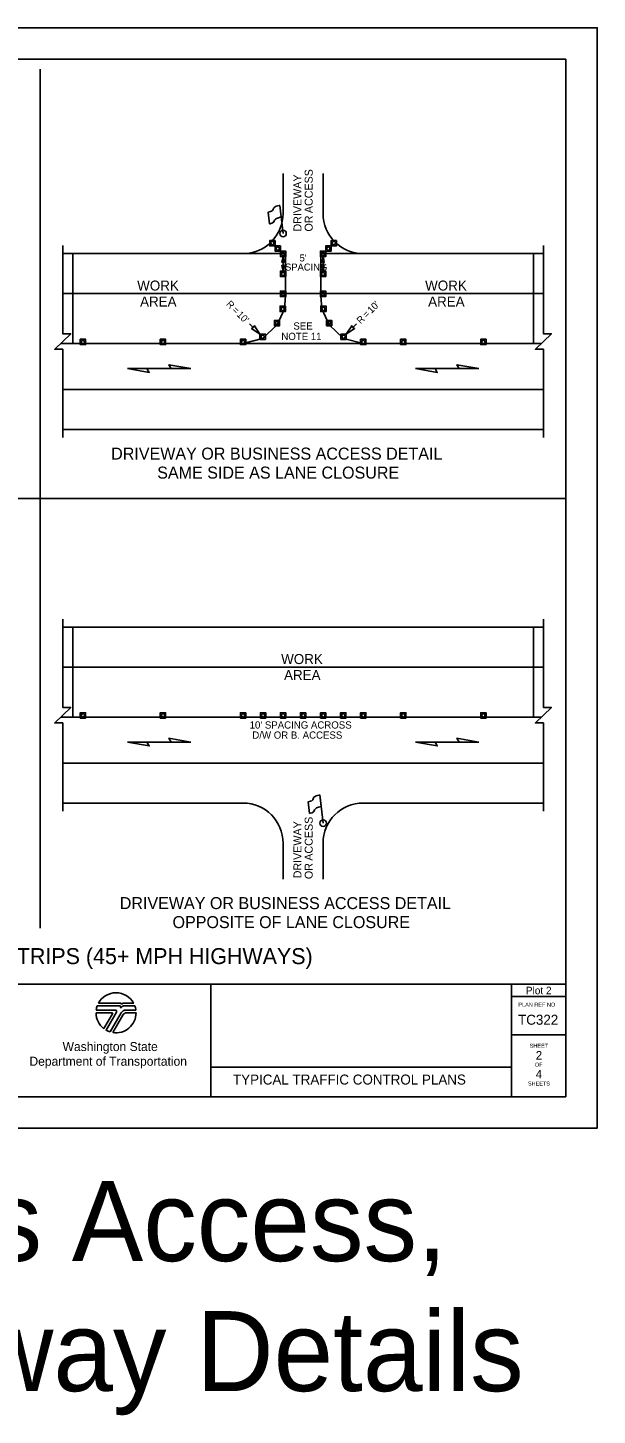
# Model space of a CAD drawing. Extents: x 99999.1 to 100095.7, y 99995 to 100010.7.
# Drawn here: x 100030.38 to 100036.06, y 99996.82 to 100010.69 of the extents above; entities that cross this region are included whole.
import ezdxf

# ---------------------------------------------------------------- set-up
doc = ezdxf.new("R2010")
doc.units = 0
for name, color, linetype in [('RD_ED_DrivewayEdge', 7, 'Continuous'), ('RD_ED_ShoulderPavedEdge', 7, 'Continuous'), ('RD_MK_LineEdgeWhite', 7, 'Continuous'), ('RD_MK_LineSkipCenter', 7, 'Continuous'), ('SH_DE_DetailHeading1Text', 7, 'Continuous'), ('SH_DE_DetailHeading2Text', 7, 'Continuous'), ('SH_GI_PlotLimits', 7, 'Continuous'), ('SH_GI_SheetBorder', 7, 'Continuous'), ('SH_GI_SheetLocationText', 7, 'Continuous'), ('SH_GI_SheetTextInCells', 7, 'Continuous'), ('SH_GI_TitleBlockText', 7, 'Continuous'), ('SH_GI_WSDOTLogo', 7, 'Continuous'), ('TR_WZ_FlaggingStation', 7, 'Continuous'), ('TR_WZ_TrafficCone', 7, 'Continuous'), ('TR_WZ_WorkAreaLabel', 7, 'Continuous'), ('TR_WZ_WorkZoneDetails', 7, 'Continuous'), ('TR_WZ_WorkZoneTextCurrent', 7, 'Continuous')]:
    doc.layers.add(name, color=color, linetype=linetype)

msp = doc.modelspace()

# ---------------------------------------------------------------- linework, layer by layer
at = {"layer": 'RD_ED_DrivewayEdge'}
for p, q in [((100032.925, 100008.83), (100032.925, 100009.23)), ((100033.325, 100008.83), (100033.325, 100009.23)), ((100032.925, 100002.536), (100032.925, 100002.176)), ((100033.325, 100002.536), (100033.325, 100002.176))]:
    msp.add_line(p, q, dxfattribs=at)
for centre, start, end in [((100032.525, 100008.83), 270, 0), ((100033.725, 100008.83), 180, 270), ((100032.525, 100002.536), 0, 90), ((100033.725, 100002.536), 90, 180)]:
    msp.add_arc(centre, 0.4, start, end, dxfattribs=at)
at = {"layer": 'RD_ED_ShoulderPavedEdge'}
for p, q in [((100030.725, 100008.43), (100032.525, 100008.43)), ((100033.725, 100008.43), (100035.525, 100008.43)), ((100030.725, 100006.67), (100035.525, 100006.67)), ((100030.725, 100004.696), (100035.525, 100004.696)), ((100030.725, 100002.936), (100032.525, 100002.936)), ((100033.725, 100002.936), (100035.525, 100002.936))]:
    msp.add_line(p, q, dxfattribs=at)
at = {"layer": 'RD_MK_LineEdgeWhite'}
for p, q in [((100030.725, 100008.03), (100035.525, 100008.03)), ((100030.725, 100007.07), (100035.525, 100007.07)), ((100030.725, 100004.296), (100035.525, 100004.296)), ((100030.725, 100003.336), (100035.525, 100003.336))]:
    msp.add_line(p, q, dxfattribs=at)
at = {"layer": 'RD_MK_LineSkipCenter'}
for points in [[(100035.504, 100007.53), (100030.704, 100007.53)], [(100035.504, 100003.796), (100030.704, 100003.796)]]:
    msp.add_lwpolyline(points, dxfattribs=at)
at = {"layer": 'SH_GI_PlotLimits'}
msp.add_lwpolyline([(100019.062, 99999.687), (100036.062, 99999.687), (100036.062, 100010.687), (100019.062, 100010.687)], close=True, dxfattribs=at)
at = {"layer": 'SH_GI_SheetBorder'}
for p, q in [((100020, 100010.375), (100035.75, 100010.375)), ((100035.75, 100010.375), (100035.75, 100000)), ((100020, 100001.126), (100035.75, 100001.126)), ((100032.205, 100001.126), (100032.205, 100000)), ((100035.208, 100001.126), (100035.208, 100000)), ((100035.208, 100001.001), (100035.75, 100001.001)), ((100035.208, 100000.618), (100035.75, 100000.618)), ((100032.205, 100000.295), (100035.208, 100000.295)), ((100020, 100000), (100035.75, 100000))]:
    msp.add_line(p, q, dxfattribs=at)
at = {"layer": 'SH_GI_WSDOTLogo'}
for p, q in [((100031.059, 100000.866), (100031.25, 100000.866)), ((100031.289, 100000.909), (100031.07, 100000.909)), ((100031.303, 100000.935), (100031.081, 100000.935)), ((100031.433, 100000.935), (100031.335, 100000.935)), ((100031.445, 100000.909), (100031.343, 100000.909)), ((100031.343, 100000.909), (100031.343, 100000.909)), ((100031.356, 100000.866), (100031.456, 100000.866)), ((100031.057, 100000.84), (100031.215, 100000.84)), ((100031.222, 100000.828), (100031.136, 100000.681)), ((100031.261, 100000.846), (100031.157, 100000.667)), ((100031.199, 100000.649), (100031.309, 100000.839)), ((100031.224, 100000.643), (100031.324, 100000.816)), ((100031.365, 100000.839), (100031.457, 100000.839))]:
    msp.add_line(p, q, dxfattribs=at)
for centre, radius, start, end in [((100031.257, 100000.84), 0.2, 28.4787, 151.532), ((100031.257, 100000.84), 0.2, 159.696, 172.5057), ((100031.25, 100000.853), 0.0131, 329.7683, 90), ((100031.289, 100000.895), 0.0148, 327.8418, 89.9985), ((100031.343, 100000.861), 0.0484, 89.9953, 147.8238), ((100031.303, 100000.926), 0.00903, 329.8742, 90.0033), ((100031.356, 100000.812), 0.0542, 90, 149.9974), ((100031.335, 100000.907), 0.0287, 90.0072, 148.1676), ((100031.257, 100000.84), 0.2, 7.4943, 20.2941), ((100031.257, 100000.84), 0.2, 179.9986, 232.8433), ((100031.215, 100000.832), 0.0082, 329.7436, 90), ((100031.257, 100000.84), 0.2, 260.5455, 359.8086), ((100031.365, 100000.792), 0.0476, 90, 150.0543), ((100031.257, 100000.84), 0.2, 239.7929, 253.0448)]:
    msp.add_arc(centre, radius, start, end, dxfattribs=at)
at = {"layer": 'TR_WZ_FlaggingStation'}
for p, q in [((100032.906, 100008.797), (100032.893, 100008.912)), ((100032.925, 100008.63), (100032.893, 100008.911)), ((100032.775, 100008.844), (100032.788, 100008.727)), ((100032.906, 100008.797), (100032.906, 100008.797)), ((100033.175, 100002.949), (100033.188, 100002.832)), ((100033.325, 100002.736), (100033.293, 100003.017)), ((100033.306, 100002.903), (100033.293, 100003.017)), ((100033.306, 100002.903), (100033.306, 100002.903))]:
    msp.add_line(p, q, dxfattribs=at)
for points in [[(100032.893, 100008.912), (100032.887, 100008.91), (100032.869, 100008.907), (100032.856, 100008.903), (100032.846, 100008.897), (100032.837, 100008.892), (100032.832, 100008.885), (100032.827, 100008.877), (100032.827, 100008.871), (100032.821, 100008.862), (100032.811, 100008.854), (100032.798, 100008.849), (100032.775, 100008.844)], [(100032.788, 100008.727), (100032.796, 100008.728), (100032.814, 100008.733), (100032.83, 100008.743), (100032.836, 100008.754), (100032.84, 100008.764), (100032.849, 100008.775), (100032.86, 100008.781), (100032.878, 100008.788), (100032.906, 100008.797)], [(100033.293, 100003.017), (100033.287, 100003.016), (100033.269, 100003.012), (100033.256, 100003.008), (100033.246, 100003.002), (100033.237, 100002.997), (100033.232, 100002.991), (100033.227, 100002.983), (100033.227, 100002.977), (100033.221, 100002.967), (100033.211, 100002.96), (100033.198, 100002.955), (100033.175, 100002.949)], [(100033.188, 100002.832), (100033.196, 100002.834), (100033.214, 100002.838), (100033.23, 100002.849), (100033.236, 100002.859), (100033.24, 100002.87), (100033.249, 100002.88), (100033.26, 100002.887), (100033.278, 100002.894), (100033.306, 100002.903)]]:
    msp.add_lwpolyline(points, dxfattribs=at)
for centre in [(100032.925, 100008.63), (100033.325, 100002.736)]:
    msp.add_circle(centre, 0.0325, dxfattribs=at)
at = {"layer": 'TR_WZ_TrafficCone'}
for points in [[(100032.845, 100008.56), (100032.845, 100008.507), (100032.792, 100008.507), (100032.792, 100008.56), (100032.845, 100008.56)], [(100032.792, 100008.56), (100032.792, 100008.507), (100032.845, 100008.507), (100032.845, 100008.56), (100032.792, 100008.56)], [(100032.898, 100008.507), (100032.898, 100008.454), (100032.845, 100008.454), (100032.845, 100008.507), (100032.898, 100008.507)], [(100032.845, 100008.507), (100032.845, 100008.454), (100032.898, 100008.454), (100032.898, 100008.507), (100032.845, 100008.507)], [(100033.352, 100008.507), (100033.352, 100008.454), (100033.405, 100008.454), (100033.405, 100008.507), (100033.352, 100008.507)], [(100033.405, 100008.507), (100033.405, 100008.454), (100033.352, 100008.454), (100033.352, 100008.507), (100033.405, 100008.507)], [(100033.405, 100008.56), (100033.405, 100008.507), (100033.458, 100008.507), (100033.458, 100008.56), (100033.405, 100008.56)], [(100033.458, 100008.56), (100033.458, 100008.507), (100033.405, 100008.507), (100033.405, 100008.56), (100033.458, 100008.56)], [(100032.898, 100008.454), (100032.952, 100008.454), (100032.952, 100008.4), (100032.898, 100008.4), (100032.898, 100008.454)], [(100032.898, 100008.4), (100032.952, 100008.4), (100032.952, 100008.454), (100032.898, 100008.454), (100032.898, 100008.4)], [(100033.352, 100008.454), (100033.298, 100008.454), (100033.298, 100008.4), (100033.352, 100008.4), (100033.352, 100008.454)], [(100033.352, 100008.4), (100033.298, 100008.4), (100033.298, 100008.454), (100033.352, 100008.454), (100033.352, 100008.4)], [(100032.898, 100008.254), (100032.952, 100008.254), (100032.952, 100008.2), (100032.898, 100008.2), (100032.898, 100008.254)], [(100032.898, 100008.2), (100032.952, 100008.2), (100032.952, 100008.254), (100032.898, 100008.254), (100032.898, 100008.2)], [(100033.352, 100008.254), (100033.298, 100008.254), (100033.298, 100008.2), (100033.352, 100008.2), (100033.352, 100008.254)], [(100033.352, 100008.2), (100033.298, 100008.2), (100033.298, 100008.254), (100033.352, 100008.254), (100033.352, 100008.2)], [(100032.898, 100008.054), (100032.952, 100008.054), (100032.952, 100008), (100032.898, 100008), (100032.898, 100008.054)], [(100032.898, 100008), (100032.952, 100008), (100032.952, 100008.054), (100032.898, 100008.054), (100032.898, 100008)], [(100033.352, 100008.054), (100033.298, 100008.054), (100033.298, 100008), (100033.352, 100008), (100033.352, 100008.054)], [(100033.352, 100008), (100033.298, 100008), (100033.298, 100008.054), (100033.352, 100008.054), (100033.352, 100008)], [(100032.896, 100007.904), (100032.949, 100007.904), (100032.949, 100007.85), (100032.896, 100007.85), (100032.896, 100007.904)], [(100032.896, 100007.85), (100032.949, 100007.85), (100032.949, 100007.904), (100032.896, 100007.904), (100032.896, 100007.85)], [(100033.354, 100007.904), (100033.301, 100007.904), (100033.301, 100007.85), (100033.354, 100007.85), (100033.354, 100007.904)], [(100033.354, 100007.85), (100033.301, 100007.85), (100033.301, 100007.904), (100033.354, 100007.904), (100033.354, 100007.85)], [(100032.838, 100007.762), (100032.891, 100007.762), (100032.891, 100007.708), (100032.838, 100007.708), (100032.838, 100007.762)], [(100032.838, 100007.708), (100032.891, 100007.708), (100032.891, 100007.762), (100032.838, 100007.762), (100032.838, 100007.708)], [(100033.412, 100007.762), (100033.359, 100007.762), (100033.359, 100007.708), (100033.412, 100007.708), (100033.412, 100007.762)], [(100033.412, 100007.708), (100033.359, 100007.708), (100033.359, 100007.762), (100033.412, 100007.762), (100033.412, 100007.708)], [(100030.899, 100007.574), (100030.952, 100007.574), (100030.952, 100007.52), (100030.899, 100007.52), (100030.899, 100007.574)], [(100030.899, 100007.52), (100030.952, 100007.52), (100030.952, 100007.574), (100030.899, 100007.574), (100030.899, 100007.52)], [(100031.699, 100007.574), (100031.752, 100007.574), (100031.752, 100007.52), (100031.699, 100007.52), (100031.699, 100007.574)], [(100031.699, 100007.52), (100031.752, 100007.52), (100031.752, 100007.574), (100031.699, 100007.574), (100031.699, 100007.52)], [(100032.499, 100007.574), (100032.552, 100007.574), (100032.552, 100007.52), (100032.499, 100007.52), (100032.499, 100007.574)], [(100032.499, 100007.52), (100032.552, 100007.52), (100032.552, 100007.574), (100032.499, 100007.574), (100032.499, 100007.52)], [(100032.694, 100007.625), (100032.748, 100007.625), (100032.748, 100007.571), (100032.694, 100007.571), (100032.694, 100007.625)], [(100032.694, 100007.571), (100032.748, 100007.571), (100032.748, 100007.625), (100032.694, 100007.625), (100032.694, 100007.571)], [(100033.556, 100007.625), (100033.502, 100007.625), (100033.502, 100007.571), (100033.556, 100007.571), (100033.556, 100007.625)], [(100033.556, 100007.571), (100033.502, 100007.571), (100033.502, 100007.625), (100033.556, 100007.625), (100033.556, 100007.571)], [(100033.699, 100007.574), (100033.752, 100007.574), (100033.752, 100007.52), (100033.699, 100007.52), (100033.699, 100007.574)], [(100033.699, 100007.52), (100033.752, 100007.52), (100033.752, 100007.574), (100033.699, 100007.574), (100033.699, 100007.52)], [(100034.099, 100007.574), (100034.152, 100007.574), (100034.152, 100007.52), (100034.099, 100007.52), (100034.099, 100007.574)], [(100034.099, 100007.52), (100034.152, 100007.52), (100034.152, 100007.574), (100034.099, 100007.574), (100034.099, 100007.52)], [(100034.899, 100007.574), (100034.952, 100007.574), (100034.952, 100007.52), (100034.899, 100007.52), (100034.899, 100007.574)], [(100034.899, 100007.52), (100034.952, 100007.52), (100034.952, 100007.574), (100034.899, 100007.574), (100034.899, 100007.52)], [(100030.899, 100003.839), (100030.952, 100003.839), (100030.952, 100003.786), (100030.899, 100003.786), (100030.899, 100003.839)], [(100030.899, 100003.786), (100030.952, 100003.786), (100030.952, 100003.839), (100030.899, 100003.839), (100030.899, 100003.786)], [(100031.699, 100003.839), (100031.752, 100003.839), (100031.752, 100003.786), (100031.699, 100003.786), (100031.699, 100003.839)], [(100031.699, 100003.786), (100031.752, 100003.786), (100031.752, 100003.839), (100031.699, 100003.839), (100031.699, 100003.786)], [(100032.499, 100003.839), (100032.552, 100003.839), (100032.552, 100003.786), (100032.499, 100003.786), (100032.499, 100003.839)], [(100032.499, 100003.786), (100032.552, 100003.786), (100032.552, 100003.839), (100032.499, 100003.839), (100032.499, 100003.786)], [(100032.699, 100003.839), (100032.752, 100003.839), (100032.752, 100003.786), (100032.699, 100003.786), (100032.699, 100003.839)], [(100032.699, 100003.786), (100032.752, 100003.786), (100032.752, 100003.839), (100032.699, 100003.839), (100032.699, 100003.786)], [(100032.899, 100003.839), (100032.952, 100003.839), (100032.952, 100003.786), (100032.899, 100003.786), (100032.899, 100003.839)], [(100032.899, 100003.786), (100032.952, 100003.786), (100032.952, 100003.839), (100032.899, 100003.839), (100032.899, 100003.786)], [(100033.099, 100003.839), (100033.152, 100003.839), (100033.152, 100003.786), (100033.099, 100003.786), (100033.099, 100003.839)], [(100033.099, 100003.786), (100033.152, 100003.786), (100033.152, 100003.839), (100033.099, 100003.839), (100033.099, 100003.786)], [(100033.299, 100003.839), (100033.352, 100003.839), (100033.352, 100003.786), (100033.299, 100003.786), (100033.299, 100003.839)], [(100033.299, 100003.786), (100033.352, 100003.786), (100033.352, 100003.839), (100033.299, 100003.839), (100033.299, 100003.786)], [(100033.499, 100003.839), (100033.552, 100003.839), (100033.552, 100003.786), (100033.499, 100003.786), (100033.499, 100003.839)], [(100033.499, 100003.786), (100033.552, 100003.786), (100033.552, 100003.839), (100033.499, 100003.839), (100033.499, 100003.786)], [(100033.699, 100003.839), (100033.752, 100003.839), (100033.752, 100003.786), (100033.699, 100003.786), (100033.699, 100003.839)], [(100033.699, 100003.786), (100033.752, 100003.786), (100033.752, 100003.839), (100033.699, 100003.839), (100033.699, 100003.786)], [(100034.099, 100003.839), (100034.152, 100003.839), (100034.152, 100003.786), (100034.099, 100003.786), (100034.099, 100003.839)], [(100034.099, 100003.786), (100034.152, 100003.786), (100034.152, 100003.839), (100034.099, 100003.839), (100034.099, 100003.786)], [(100034.899, 100003.839), (100034.952, 100003.839), (100034.952, 100003.786), (100034.899, 100003.786), (100034.899, 100003.839)], [(100034.899, 100003.786), (100034.952, 100003.786), (100034.952, 100003.839), (100034.899, 100003.839), (100034.899, 100003.786)]]:
    msp.add_lwpolyline(points, dxfattribs=at)
for centre in [(100032.818, 100008.534), (100032.872, 100008.48), (100033.378, 100008.48), (100033.432, 100008.534), (100032.925, 100008.427), (100033.325, 100008.427), (100032.925, 100008.227), (100033.325, 100008.227), (100032.925, 100008.027), (100033.325, 100008.027), (100032.922, 100007.877), (100033.328, 100007.877), (100032.865, 100007.735), (100033.385, 100007.735), (100030.926, 100007.547), (100031.726, 100007.547), (100032.526, 100007.547), (100032.721, 100007.598), (100033.529, 100007.598), (100033.726, 100007.547), (100034.126, 100007.547), (100034.926, 100007.547), (100030.926, 100003.813), (100031.726, 100003.813), (100032.526, 100003.813), (100032.726, 100003.813), (100032.926, 100003.813), (100033.126, 100003.813), (100033.326, 100003.813), (100033.526, 100003.813), (100033.726, 100003.813), (100034.126, 100003.813), (100034.926, 100003.813)]:
    msp.add_circle(centre, 0.0167, dxfattribs=at)
at = {"layer": 'TR_WZ_WorkZoneDetails'}
for p, q in [((100030.5, 100010.275), (100030.5, 100001.686)), ((100032.925, 100008.346), (100032.925, 100008.308)), ((100033.325, 100008.346), (100033.325, 100008.308)), ((100032.628, 100007.691), (100032.59, 100007.729)), ((100033.622, 100007.691), (100033.66, 100007.729)), ((100031.566, 100007.28), (100031.808, 100007.28)), ((100031.808, 100007.28), (100031.566, 100007.28)), ((100034.443, 100007.28), (100034.684, 100007.28)), ((100034.684, 100007.28), (100034.443, 100007.28)), ((100030.5, 100005.98), (100025.25, 100005.98)), ((100035.75, 100005.98), (100030.5, 100005.98)), ((100031.566, 100003.546), (100031.808, 100003.546)), ((100031.808, 100003.546), (100031.566, 100003.546)), ((100034.443, 100003.546), (100034.684, 100003.546)), ((100034.684, 100003.546), (100034.443, 100003.546))]:
    msp.add_line(p, q, dxfattribs=at)
for points in [[(100030.725, 100006.59), (100030.725, 100007.473), (100030.645, 100007.473), (100030.805, 100007.628), (100030.725, 100007.628), (100030.725, 100008.51)], [(100035.525, 100006.59), (100035.525, 100007.473), (100035.445, 100007.473), (100035.605, 100007.628), (100035.525, 100007.628), (100035.525, 100008.51)], [(100030.725, 100002.856), (100030.725, 100003.738), (100030.645, 100003.738), (100030.805, 100003.893), (100030.725, 100003.893), (100030.725, 100004.776)], [(100035.525, 100002.856), (100035.525, 100003.738), (100035.445, 100003.738), (100035.605, 100003.893), (100035.525, 100003.893), (100035.525, 100004.776)]]:
    msp.add_lwpolyline(points, dxfattribs=at)
for points in [[(100032.948, 100008.43), (100032.948, 100008.207), (100032.948, 100008.007), (100032.939, 100007.877), (100032.939, 100007.877), (100032.939, 100007.877), (100032.865, 100007.718), (100032.865, 100007.718), (100032.865, 100007.718), (100032.721, 100007.581), (100032.526, 100007.53), (100031.529, 100007.53), (100030.949, 100007.53), (100030.825, 100007.53), (100030.825, 100008.43)], [(100032.925, 100008.4), (100032.936, 100008.343), (100032.925, 100008.346), (100032.914, 100008.343)], [(100035.425, 100008.43), (100035.425, 100008.03), (100035.425, 100007.53), (100034.501, 100007.53), (100034.501, 100007.53), (100034.501, 100007.53), (100033.726, 100007.53), (100033.726, 100007.53), (100033.726, 100007.53), (100033.529, 100007.581), (100033.385, 100007.718), (100033.311, 100007.877), (100033.302, 100008.007), (100033.302, 100008.207), (100033.302, 100008.43)], [(100033.325, 100008.4), (100033.336, 100008.343), (100033.325, 100008.346), (100033.314, 100008.343)], [(100032.925, 100008.254), (100032.936, 100008.311), (100032.925, 100008.308), (100032.914, 100008.311)], [(100033.325, 100008.254), (100033.336, 100008.311), (100033.325, 100008.308), (100033.314, 100008.311)], [(100032.694, 100007.625), (100032.611, 100007.681), (100032.628, 100007.691), (100032.639, 100007.708)], [(100033.556, 100007.625), (100033.639, 100007.681), (100033.622, 100007.691), (100033.611, 100007.708)], [(100031.37, 100007.28), (100031.589, 100007.242), (100031.566, 100007.28)], [(100032.004, 100007.28), (100031.785, 100007.319), (100031.808, 100007.28)], [(100034.247, 100007.28), (100034.465, 100007.242), (100034.443, 100007.28)], [(100034.881, 100007.28), (100034.662, 100007.319), (100034.684, 100007.28)], [(100030.825, 100004.696), (100030.825, 100003.796), (100035.425, 100003.796), (100035.425, 100004.696)], [(100031.37, 100003.546), (100031.589, 100003.507), (100031.566, 100003.546)], [(100032.004, 100003.546), (100031.785, 100003.584), (100031.808, 100003.546)], [(100034.247, 100003.546), (100034.465, 100003.507), (100034.443, 100003.546)], [(100034.881, 100003.546), (100034.662, 100003.584), (100034.684, 100003.546)]]:
    msp.add_lwpolyline(points, close=True, dxfattribs=at)

# ---------------------------------------------------------------- texts
at = {"layer": 'SH_DE_DetailHeading1Text'}
msp.add_text('ALTERNATING 1-LANE, 2-WAY TRAFFIC: FLAGGER-CONTROLLED + TEMP. RUMBLE STRIPS (45+ MPH HIGHWAYS)', height=0.16, rotation=360, dxfattribs=at).set_placement((100021.475, 100001.326))
at = {"layer": 'SH_DE_DetailHeading2Text'}
for s, p in [('DRIVEWAY OR BUSINESS ACCESS DETAIL', (100031.208, 100006.37)), ('SAME SIDE AS LANE CLOSURE', (100031.668, 100006.18)), ('DRIVEWAY OR BUSINESS ACCESS DETAIL', (100031.294, 100001.876)), ('OPPOSITE OF LANE CLOSURE', (100031.821, 100001.686))]:
    msp.add_text(s, height=0.12, rotation=360, dxfattribs=at).set_placement(p)
at = {"layer": 'SH_GI_SheetBorder'}
msp.add_text('PLAN REF NO', height=0.04003, dxfattribs=at).set_placement((100035.275, 100000.901))
at = {"layer": 'SH_GI_SheetLocationText'}
for s, height, p in [('Plot 2', 0.075, (100035.35, 100001.025)), ('Driveway, Business Access,', 0.8, (100021.184, 99998.357)), ('or Intersecting Roadway Details', 0.8, (100020.225, 99997.057))]:
    msp.add_text(s, height=height, dxfattribs=at).set_placement(p)
at = {"layer": 'SH_GI_SheetTextInCells'}
for s, height, p in [('Washington State', 0.09007, (100030.723, 100000.457)), ('SHEET', 0.04, (100035.388, 100000.49)), ('Department of Transportation', 0.09007, (100030.392, 100000.31)), ('OF', 0.04, (100035.441, 100000.301)), ('SHEETS', 0.04, (100035.37, 100000.112))]:
    msp.add_text(s, height=height, dxfattribs=at).set_placement(p)
at = {"layer": 'SH_GI_TitleBlockText'}
for s, height, p in [('TC322', 0.1, (100035.272, 100000.72)), ('2', 0.085, (100035.449, 100000.372)), ('TYPICAL TRAFFIC CONTROL PLANS', 0.1, (100032.425, 100000.122)), ('4', 0.085, (100035.449, 100000.184))]:
    msp.add_text(s, height=height, dxfattribs=at).set_placement(p)
at = {"layer": 'TR_WZ_WorkAreaLabel'}
for s, p in [('WORK', (100031.468, 100008.06)), ('WORK', (100034.344, 100008.06)), ('AREA', (100031.497, 100007.9)), ('AREA', (100034.374, 100007.9)), ('WORK', (100032.906, 100004.326)), ('AREA', (100032.935, 100004.166))]:
    msp.add_text(s, height=0.1, dxfattribs=at).set_placement(p)
at = {"layer": 'TR_WZ_WorkZoneTextCurrent'}
for s, height, rotation, p in [('DRIVEWAY', 0.08, 90, (100033.109, 100008.65)), ('ACCESS', 0.08, 90, (100033.221, 100008.834)), ('OR', 0.08, 90, (100033.221, 100008.65)), ('R', 0.07, 315, (100032.351, 100007.919)), ("10'", 0.07, 45, (100033.808, 100007.827)), ('=', 0.07, 315, (100032.41, 100007.859)), ("10'", 0.07, 315, (100032.457, 100007.813)), ('R', 0.07, 45, (100033.701, 100007.721)), ('=', 0.07, 45, (100033.761, 100007.78)), ('ACCESS', 0.08, 90, (100033.221, 100002.36)), ('DRIVEWAY', 0.08, 90, (100033.109, 100002.184)), ('OR', 0.08, 90, (100033.221, 100002.176))]:
    msp.add_text(s, height=height, rotation=rotation, dxfattribs=at).set_placement(p)
for s, height, p in [("5'", 0.07, (100033.09, 100008.351)), ('SPACING', 0.07, (100032.945, 100008.26)), ('SEE', 0.072, (100033.028, 100007.67)), ('NOTE 11', 0.072, (100032.908, 100007.566)), ("10' SPACING ACROSS", 0.072, (100032.591, 100003.681)), ('D/W OR B. ACCESS', 0.072, (100032.618, 100003.58))]:
    msp.add_text(s, height=height, dxfattribs=at).set_placement(p)

doc.saveas('drawing.dxf')
